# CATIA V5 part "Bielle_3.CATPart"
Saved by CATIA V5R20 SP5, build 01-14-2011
Part number: Bielle_3
Publications: "Droite.1", "Droite.2", "Droite.3", "Droite.4"
Bounding box of the stored display mesh (mm): x 0 to 200, y 300 to 618.933, z -74 to 128.204
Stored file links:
  J:\Thinkmotion\Projet IAO\A envoyer\Bielle_3.CATPart
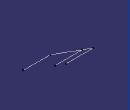
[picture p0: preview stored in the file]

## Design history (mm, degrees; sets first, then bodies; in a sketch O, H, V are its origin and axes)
Set1
  Line1: type PtPt, FirstPoint Point11, SecondPoint Point2
  Point1 "C": stored without definition
  Point2 "E": stored without definition
  Line2: type Normal, RefPoint Point9, RefSkin yz-plane, Start 0, End 200
  Point3 "C": stored without definition
  Line3: type Normal, RefPoint Point4, RefSkin yz-plane, Start 0, End 200
  Point4 "E": stored without definition
  Line4: type Normal, RefPoint Point10, RefSkin yz-plane, Start 0, End 200
  Point5 to Point8 "D": stored without definition
  Point9 "C": stored without definition
  Point10 "D": stored without definition
  Point11 "C": stored without definition
Body1 (main body)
